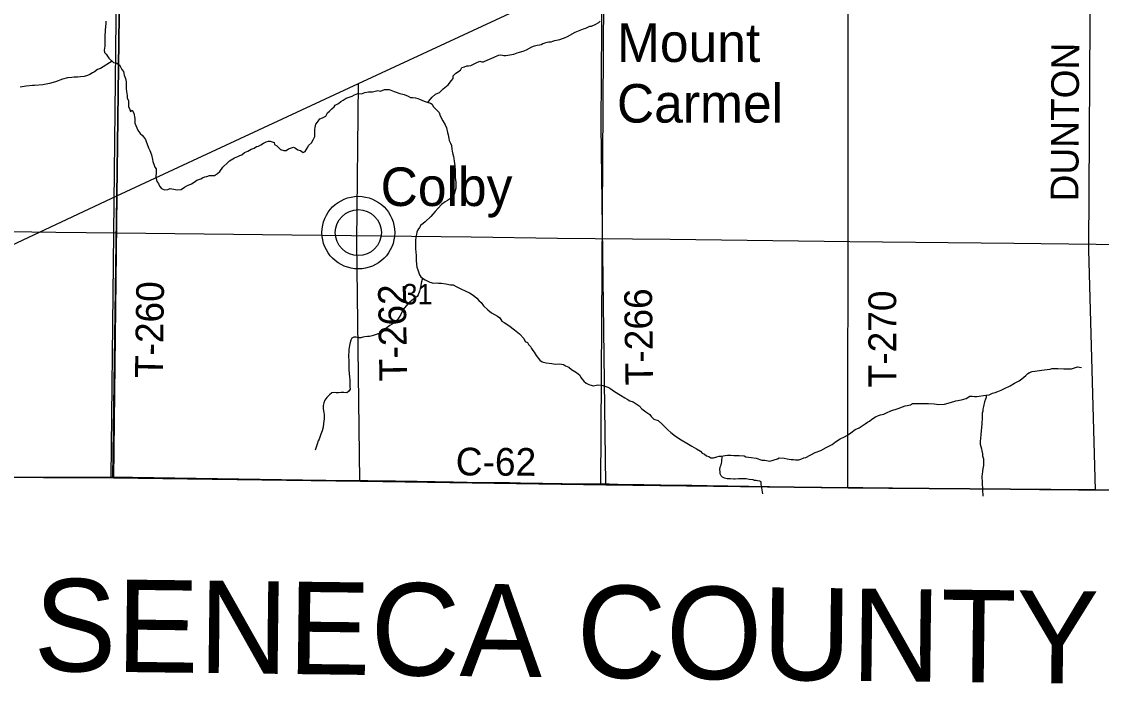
# Model space of a CAD drawing. Extents: x 1588073 to 2013523, y 1090242 to 1357120.
# Drawn here: x 1842074 to 1853753, y 1184232 to 1191391 of the extents above; entities that cross this region are included whole.
import ezdxf

# ---------------------------------------------------------------- set-up
doc = ezdxf.new("R2010")
doc.units = 0
for name, color, linetype in [('GM_X_Adjacent_County', 7, 'Continuous'), ('GM_X_Adjacent_County_Text', 7, 'Continuous'), ('GM_X_County', 7, 'Continuous'), ('GM_X_County_Road', 7, 'Continuous'), ('GM_X_County_Road_Text', 7, 'Continuous'), ('GM_X_Minor_River', 7, 'Continuous'), ('GM_X_Rail_Line', 7, 'Continuous'), ('GM_X_Section', 7, 'Continuous'), ('GM_X_Section_Text', 7, 'Continuous'), ('GM_X_Township', 7, 'Continuous'), ('GM_X_Township_Road', 7, 'Continuous'), ('GM_X_Township_Road_Text', 7, 'Continuous'), ('GM_X_Unincorporated', 7, 'Continuous'), ('GM_X_Unincorporated_Location', 7, 'Continuous'), ('GM_X_Unincorporated_Text', 7, 'Continuous')]:
    doc.layers.add(name, color=color, linetype=linetype)

msp = doc.modelspace()

# ---------------------------------------------------------------- linework, layer by layer
at = {"layer": 'GM_X_Adjacent_County'}
msp.add_lwpolyline([(1808199, 1186945), (1810942, 1186950), (1813328, 1186914), (1815460, 1186869), (1816005, 1186857), (1816631, 1186848), (1817077, 1186838), (1817700, 1186826), (1818180, 1186810), (1818871, 1186791), (1819168, 1186784), (1821835, 1186718), (1827562, 1186497), (1829633, 1186472), (1832499, 1186486), (1836614, 1186490), (1837772, 1186480), (1843068, 1186456), (1845738, 1186419), (1848393, 1186378), (1851014, 1186349), (1853645, 1186324), (1853690, 1186324), (1859011, 1186262)], dxfattribs=at)
at = {"layer": 'GM_X_County'}
msp.add_lwpolyline([(1859011, 1186262), (1853690, 1186324), (1853645, 1186324), (1851014, 1186349), (1848393, 1186378), (1845738, 1186419), (1843068, 1186456), (1837772, 1186480), (1836614, 1186490), (1832499, 1186486), (1829633, 1186472), (1827562, 1186497), (1821835, 1186718), (1819168, 1186784), (1818871, 1186791), (1818180, 1186810), (1817700, 1186826), (1817077, 1186838), (1816631, 1186848), (1816005, 1186857), (1815460, 1186869), (1813328, 1186914), (1810942, 1186950), (1808199, 1186945)], dxfattribs=at)
at = {"layer": 'GM_X_County_Road'}
for points in [[(1843105, 1189507), (1845717, 1190720), (1847202, 1191411), (1847662, 1191625), (1848323, 1191951), (1851017, 1193279)], [(1837774, 1187005), (1843105, 1189507)], [(1836617, 1186499), (1836629, 1186498), (1836740, 1186495), (1837115, 1186492), (1837367, 1186488), (1837499, 1186487), (1837760, 1186486), (1837991, 1186485), (1838381, 1186482), (1838864, 1186479), (1839379, 1186477), (1839648, 1186476), (1839977, 1186474), (1840154, 1186474), (1840466, 1186472), (1840866, 1186471), (1841335, 1186469), (1841608, 1186468), (1841825, 1186467), (1842586, 1186464), (1842776, 1186463), (1843060, 1186461)], [(1843060, 1186461), (1843072, 1186461), (1843777, 1186452), (1843879, 1186451), (1844266, 1186445), (1844558, 1186440), (1844749, 1186438), (1844985, 1186434), (1845366, 1186429), (1845733, 1186426), (1845819, 1186426), (1846117, 1186422), (1846354, 1186419), (1846741, 1186412), (1847046, 1186406), (1847256, 1186405), (1847351, 1186404), (1847591, 1186399), (1847709, 1186398), (1847919, 1186395), (1848247, 1186390), (1848375, 1186389), (1848394, 1186389)], [(1848394, 1186389), (1848428, 1186389), (1848615, 1186384), (1848805, 1186382), (1848989, 1186380), (1849189, 1186377), (1849324, 1186375), (1849488, 1186373), (1850164, 1186360), (1850315, 1186359), (1850508, 1186356), (1850728, 1186354), (1850951, 1186352), (1851010, 1186352), (1851171, 1186351), (1851492, 1186346), (1851843, 1186343), (1852093, 1186340), (1852569, 1186336), (1852815, 1186332), (1853084, 1186329), (1853504, 1186326), (1853637, 1186325), (1853689, 1186325)], [(1853689, 1186325), (1853747, 1186324), (1853980, 1186321), (1854220, 1186319), (1854505, 1186316), (1854725, 1186314), (1855017, 1186312), (1855303, 1186309), (1855657, 1186305), (1855893, 1186302), (1856034, 1186301), (1856454, 1186296), (1856947, 1186290), (1857291, 1186286), (1857551, 1186282), (1857757, 1186279), (1857899, 1186278), (1858056, 1186276), (1858197, 1186275), (1858342, 1186272), (1858526, 1186270), (1858729, 1186268), (1858890, 1186267), (1858998, 1186266)]]:
    msp.add_lwpolyline(points, dxfattribs=at)
at = {"layer": 'GM_X_Minor_River'}
for points in [[(1842986, 1191395), (1842984, 1191375), (1842982, 1191334), (1842978, 1191300), (1842978, 1191276), (1842976, 1191252), (1842975, 1191214), (1842975, 1191156), (1842973, 1191126), (1842971, 1191104), (1842967, 1191082), (1842971, 1191058), (1842988, 1191038), (1843018, 1190994), (1843068, 1190950), (1843104, 1190940), (1843134, 1190922), (1843159, 1190874), (1843177, 1190852), (1843181, 1190832), (1843183, 1190810), (1843197, 1190774), (1843206, 1190740), (1843206, 1190664), (1843210, 1190634), (1843214, 1190593), (1843216, 1190565), (1843229, 1190535), (1843229, 1190515), (1843231, 1190473), (1843243, 1190441), (1843251, 1190417), (1843271, 1190433), (1843289, 1190401), (1843300, 1190341), (1843300, 1190293), (1843308, 1190265), (1843330, 1190217), (1843357, 1190181), (1843383, 1190157), (1843415, 1190115), (1843421, 1190095), (1843431, 1190065), (1843446, 1190025), (1843462, 1189995), (1843478, 1189949), (1843490, 1189899), (1843494, 1189877), (1843509, 1189839), (1843515, 1189817), (1843529, 1189797), (1843531, 1189777), (1843531, 1189755), (1843527, 1189714), (1843529, 1189694), (1843538, 1189662), (1843554, 1189638), (1843564, 1189610), (1843586, 1189584), (1843618, 1189572), (1843654, 1189575), (1843682, 1189585), (1843739, 1189575), (1843761, 1189571), (1843799, 1189575), (1843837, 1189598), (1843869, 1189616), (1843911, 1189634), (1843939, 1189654), (1843968, 1189676), (1844011, 1189691), (1844031, 1189699), (1844054, 1189711), (1844079, 1189715), (1844105, 1189725), (1844131, 1189725), (1844161, 1189727), (1844191, 1189748), (1844217, 1189770), (1844252, 1189816), (1844304, 1189867), (1844324, 1189885), (1844378, 1189917), (1844414, 1189933), (1844436, 1189943), (1844456, 1189951), (1844486, 1189976), (1844520, 1189988), (1844558, 1190010), (1844590, 1190020), (1844616, 1190038), (1844636, 1190043), (1844660, 1190059), (1844692, 1190075), (1844720, 1190091), (1844744, 1190097), (1844764, 1190097), (1844784, 1190091)], [(1846465, 1190518), (1846475, 1190527), (1846515, 1190573), (1846551, 1190605), (1846595, 1190622), (1846634, 1190664), (1846670, 1190694), (1846686, 1190708), (1846723, 1190754), (1846741, 1190775), (1846743, 1190803), (1846771, 1190833), (1846820, 1190865), (1846836, 1190895), (1846864, 1190901), (1846890, 1190912), (1846906, 1190912), (1846934, 1190916), (1846991, 1190946), (1847029, 1190963), (1847051, 1190955), (1847069, 1190957), (1847083, 1190961), (1847133, 1190984), (1847185, 1191006), (1847232, 1191026), (1847250, 1191030), (1847274, 1191027), (1847290, 1191025), (1847310, 1191025), (1847332, 1191027), (1847396, 1191038), (1847434, 1191054), (1847458, 1191060), (1847498, 1191071), (1847534, 1191085), (1847591, 1191117), (1847621, 1191127), (1847649, 1191134), (1847675, 1191140), (1847693, 1191144), (1847711, 1191152), (1847727, 1191158), (1847743, 1191164), (1847757, 1191167), (1847777, 1191171), (1847801, 1191173), (1847820, 1191179), (1847842, 1191185), (1847894, 1191198), (1847924, 1191208), (1847946, 1191216), (1847978, 1191228), (1848061, 1191277), (1848097, 1191289), (1848151, 1191312), (1848175, 1191320), (1848221, 1191340), (1848237, 1191342), (1848278, 1191361), (1848316, 1191381), (1848330, 1191395)], [(1843052, 1190964), (1842926, 1190885), (1842894, 1190873), (1842862, 1190846), (1842840, 1190838), (1842812, 1190820), (1842788, 1190806), (1842752, 1190796), (1842710, 1190792), (1842678, 1190791), (1842644, 1190789), (1842616, 1190785), (1842572, 1190781), (1842518, 1190767), (1842442, 1190738), (1842374, 1190722), (1842302, 1190707), (1842214, 1190701), (1842192, 1190701), (1842123, 1190694), (1842057, 1190682)], [(1844784, 1190091), (1844804, 1190084), (1844810, 1190063), (1844834, 1190048), (1844855, 1190024), (1844875, 1190008), (1844909, 1189996), (1844935, 1189998), (1844959, 1190016), (1844983, 1190022), (1845015, 1190032), (1845035, 1190020), (1845063, 1190005), (1845089, 1189995), (1845121, 1189975), (1845141, 1189985), (1845151, 1190005), (1845171, 1190031), (1845177, 1190051), (1845211, 1190079), (1845229, 1190110), (1845245, 1190148), (1845244, 1190224), (1845250, 1190244), (1845258, 1190282), (1845276, 1190302), (1845300, 1190339), (1845330, 1190349), (1845366, 1190369), (1845384, 1190405), (1845404, 1190423), (1845428, 1190446), (1845454, 1190468), (1845466, 1190488), (1845500, 1190504), (1845525, 1190528), (1845551, 1190540), (1845583, 1190561), (1845605, 1190571), (1845649, 1190585), (1845675, 1190599), (1845709, 1190613), (1845752, 1190610), (1845788, 1190624), (1845826, 1190630), (1845870, 1190632), (1845926, 1190646), (1845956, 1190639), (1846000, 1190657), (1846022, 1190655), (1846050, 1190657), (1846104, 1190635), (1846166, 1190614), (1846213, 1190602), (1846255, 1190584), (1846281, 1190570), (1846307, 1190568), (1846335, 1190566), (1846359, 1190558), (1846379, 1190552), (1846429, 1190531), (1846461, 1190519), (1846496, 1190509), (1846516, 1190497), (1846524, 1190471), (1846558, 1190441), (1846590, 1190409), (1846601, 1190371), (1846631, 1190319), (1846655, 1190275), (1846669, 1190241), (1846682, 1190191), (1846686, 1190167), (1846696, 1190127), (1846700, 1190105), (1846714, 1190077), (1846722, 1190051), (1846729, 1190010), (1846731, 1189990), (1846739, 1189956), (1846745, 1189932), (1846749, 1189910), (1846753, 1189880), (1846758, 1189830), (1846762, 1189778), (1846762, 1189750), (1846764, 1189704), (1846768, 1189680), (1846770, 1189654), (1846771, 1189632), (1846769, 1189612), (1846769, 1189589), (1846765, 1189563), (1846755, 1189535), (1846733, 1189501), (1846701, 1189471), (1846681, 1189455), (1846655, 1189441), (1846617, 1189412), (1846580, 1189374), (1846548, 1189336)], [(1846548, 1189336), (1846520, 1189309), (1846500, 1189283), (1846440, 1189223), (1846416, 1189207), (1846392, 1189187), (1846376, 1189164), (1846360, 1189138), (1846350, 1189114), (1846346, 1189090), (1846339, 1189056), (1846335, 1189028), (1846333, 1188986), (1846335, 1188940), (1846339, 1188889), (1846342, 1188869), (1846342, 1188807), (1846344, 1188765), (1846350, 1188735), (1846358, 1188707), (1846367, 1188685), (1846377, 1188653), (1846391, 1188629), (1846419, 1188607), (1846439, 1188599), (1846491, 1188573), (1846529, 1188561), (1846556, 1188564), (1846584, 1188560), (1846614, 1188562), (1846664, 1188554), (1846712, 1188544), (1846742, 1188542), (1846774, 1188524), (1846826, 1188501), (1846879, 1188475), (1846917, 1188457), (1846959, 1188431), (1846997, 1188399), (1847021, 1188375), (1847044, 1188351), (1847070, 1188317), (1847116, 1188271), (1847158, 1188239), (1847221, 1188204), (1847245, 1188188), (1847269, 1188150), (1847293, 1188134), (1847343, 1188104), (1847406, 1188056), (1847460, 1188014), (1847505, 1187964), (1847521, 1187932), (1847545, 1187918), (1847557, 1187896), (1847577, 1187876), (1847589, 1187856), (1847603, 1187834), (1847618, 1187814), (1847638, 1187778), (1847680, 1187730), (1847704, 1187711), (1847748, 1187701), (1847809, 1187693), (1847845, 1187685), (1847889, 1187687), (1847913, 1187685), (1847935, 1187682), (1847957, 1187668), (1847991, 1187652), (1848023, 1187628), (1848076, 1187594), (1848110, 1187566), (1848124, 1187542), (1848138, 1187522), (1848154, 1187502), (1848180, 1187480), (1848200, 1187470), (1848221, 1187462), (1848259, 1187452), (1848307, 1187463), (1848337, 1187457), (1848361, 1187455), (1848393, 1187443), (1848413, 1187437), (1848435, 1187425), (1848487, 1187389), (1848550, 1187350), (1848600, 1187320), (1848624, 1187308), (1848654, 1187290), (1848690, 1187276), (1848731, 1187248), (1848755, 1187234), (1848783, 1187202), (1848825, 1187168), (1848868, 1187140), (1848884, 1187118), (1848912, 1187091), (1848958, 1187075), (1849002, 1187035)], [(1846410, 1188614), (1846397, 1188563), (1846393, 1188535), (1846385, 1188503), (1846378, 1188476), (1846364, 1188436), (1846352, 1188416), (1846308, 1188386), (1846276, 1188360), (1846250, 1188337), (1846202, 1188277), (1846190, 1188253), (1846176, 1188223), (1846159, 1188193), (1846135, 1188162), (1846111, 1188138), (1846083, 1188118), (1846057, 1188102), (1846029, 1188082), (1846005, 1188063), (1845975, 1188037), (1845953, 1188025), (1845929, 1188013), (1845887, 1187997), (1845867, 1187993), (1845835, 1187986), (1845815, 1187984), (1845785, 1187980), (1845765, 1187976), (1845743, 1187970), (1845719, 1187970), (1845693, 1187976), (1845669, 1187978), (1845647, 1187967), (1845635, 1187945), (1845627, 1187921), (1845621, 1187887), (1845617, 1187865), (1845615, 1187843), (1845613, 1187817), (1845611, 1187781), (1845612, 1187711), (1845614, 1187676), (1845614, 1187652), (1845614, 1187622), (1845621, 1187544), (1845623, 1187516), (1845623, 1187494), (1845625, 1187470), (1845625, 1187440), (1845627, 1187416), (1845611, 1187390), (1845591, 1187376), (1845559, 1187377), (1845531, 1187379), (1845501, 1187375), (1845475, 1187375), (1845455, 1187377), (1845431, 1187375), (1845403, 1187353), (1845375, 1187326), (1845353, 1187294), (1845343, 1187268), (1845336, 1187238), (1845334, 1187206), (1845340, 1187182), (1845344, 1187162), (1845348, 1187140), (1845348, 1187118), (1845346, 1187092), (1845339, 1187045), (1845335, 1187005), (1845325, 1186963), (1845311, 1186927), (1845299, 1186897), (1845291, 1186875), (1845283, 1186855), (1845270, 1186818), (1845262, 1186798), (1845250, 1186754)], [(1849002, 1187035), (1849065, 1186973), (1849095, 1186947), (1849147, 1186905), (1849208, 1186865), (1849268, 1186832), (1849322, 1186798), (1849374, 1186770), (1849417, 1186744), (1849433, 1186724), (1849461, 1186710), (1849483, 1186694), (1849505, 1186686), (1849527, 1186672), (1849557, 1186672), (1849595, 1186683), (1849617, 1186689), (1849637, 1186689), (1849710, 1186701), (1849744, 1186699), (1849778, 1186696), (1849812, 1186698), (1849836, 1186698), (1849888, 1186692), (1849908, 1186682), (1849966, 1186674), (1850018, 1186669), (1850079, 1186647), (1850111, 1186647), (1850165, 1186637), (1850249, 1186662), (1850269, 1186672), (1850323, 1186670), (1850355, 1186662), (1850375, 1186656), (1850399, 1186654), (1850423, 1186654), (1850445, 1186651), (1850481, 1186649), (1850503, 1186657), (1850535, 1186671), (1850557, 1186677), (1850657, 1186728), (1850717, 1186750), (1850775, 1186783), (1850839, 1186815), (1850877, 1186845), (1850929, 1186878), (1850975, 1186900), (1851007, 1186918), (1851043, 1186944), (1851091, 1186977), (1851133, 1186995), (1851155, 1187009), (1851199, 1187041), (1851223, 1187059), (1851245, 1187070), (1851269, 1187090), (1851311, 1187116), (1851343, 1187128), (1851363, 1187136), (1851401, 1187145), (1851427, 1187157), (1851477, 1187179), (1851553, 1187205), (1851603, 1187222), (1851631, 1187234), (1851653, 1187238), (1851687, 1187246), (1851709, 1187258), (1851765, 1187261), (1851787, 1187259), (1851881, 1187259), (1851945, 1187255), (1851996, 1187250), (1852056, 1187254), (1852122, 1187270), (1852178, 1187289), (1852238, 1187299), (1852290, 1187315), (1852330, 1187338), (1852354, 1187338), (1852380, 1187336), (1852404, 1187334), (1852502, 1187348), (1852540, 1187355), (1852576, 1187373), (1852604, 1187377), (1852632, 1187389), (1852668, 1187403), (1852706, 1187422), (1852766, 1187450), (1852814, 1187478), (1852862, 1187504), (1852892, 1187525), (1852914, 1187545), (1852936, 1187563), (1852956, 1187585), (1852976, 1187595), (1853002, 1187605), (1853032, 1187610)], [(1853032, 1187610), (1853058, 1187614), (1853134, 1187624), (1853198, 1187632), (1853218, 1187637), (1853280, 1187639), (1853346, 1187635), (1853387, 1187633), (1853431, 1187636), (1853471, 1187648), (1853495, 1187656), (1853515, 1187654), (1853537, 1187650)], [(1852507, 1187349), (1852506, 1187326), (1852500, 1187306), (1852488, 1187278), (1852477, 1187228), (1852471, 1187200), (1852469, 1187176), (1852463, 1187154), (1852463, 1187087), (1852461, 1187057), (1852458, 1187037), (1852456, 1187003), (1852452, 1186959), (1852448, 1186927), (1852444, 1186877), (1852442, 1186855), (1852443, 1186819), (1852447, 1186794), (1852455, 1186768), (1852459, 1186746), (1852465, 1186714), (1852465, 1186694), (1852476, 1186662), (1852478, 1186620), (1852476, 1186590), (1852470, 1186556), (1852468, 1186524), (1852462, 1186496), (1852460, 1186474), (1852471, 1186258)], [(1850090, 1186283), (1850076, 1186368), (1850074, 1186384), (1850074, 1186398), (1850072, 1186414), (1850058, 1186418), (1850034, 1186422), (1850018, 1186426), (1850000, 1186428), (1849986, 1186435), (1849942, 1186439), (1849912, 1186445), (1849860, 1186446), (1849826, 1186446), (1849792, 1186440), (1849778, 1186440), (1849742, 1186443), (1849724, 1186443), (1849706, 1186445), (1849692, 1186447), (1849676, 1186453), (1849656, 1186464), (1849640, 1186478), (1849631, 1186498), (1849629, 1186516), (1849625, 1186548), (1849629, 1186566), (1849633, 1186580), (1849639, 1186596), (1849644, 1186614), (1849646, 1186628), (1849651, 1186692)]]:
    msp.add_lwpolyline(points, dxfattribs=at)
at = {"layer": 'GM_X_Rail_Line'}
msp.add_lwpolyline([(1841662, 1189122), (1842445, 1189112), (1843102, 1189104), (1844995, 1189084), (1846935, 1189062), (1847871, 1189049), (1849087, 1189036), (1851031, 1189012), (1852804, 1188993), (1853696, 1188983), (1855356, 1188964)], dxfattribs=at)
at = {"layer": 'GM_X_Section'}
msp.add_lwpolyline([(1843101, 1191744), (1848366, 1191654), (1848334, 1186381), (1843042, 1186461)], close=True, dxfattribs=at)
at = {"layer": 'GM_X_Township'}
for points in [[(1822454, 1217980), (1826179, 1218043), (1826396, 1218046), (1832767, 1218132), (1832904, 1218134), (1838096, 1218217), (1843456, 1218285), (1843390, 1212953), (1843338, 1209236), (1843273, 1204127), (1843209, 1199148), (1843132, 1191734), (1843105, 1189507), (1843068, 1186456), (1837772, 1186480), (1836614, 1186490), (1832499, 1186486), (1829633, 1186472), (1827562, 1186497), (1821835, 1186718)], [(1859011, 1186262), (1853690, 1186324), (1853645, 1186324), (1851014, 1186349), (1848393, 1186378), (1845738, 1186419), (1843068, 1186456), (1843105, 1189507), (1843132, 1191734), (1843209, 1199148), (1843273, 1204127), (1843338, 1209236), (1843390, 1212953), (1843456, 1218285), (1848744, 1218244), (1854040, 1218203)]]:
    msp.add_lwpolyline(points, dxfattribs=at)
at = {"layer": 'GM_X_Township_Road'}
for points in [[(1853615, 1188940), (1853642, 1193230), (1853649, 1194371)], [(1851010, 1186352), (1851017, 1193279)], [(1848394, 1186389), (1848343, 1190268), (1848352, 1191871), (1848351, 1191893), (1848323, 1191951)], [(1843060, 1186461), (1843105, 1189507), (1843132, 1191734)], [(1845701, 1189013), (1845717, 1190720)], [(1845733, 1186426), (1845701, 1188996), (1845701, 1189013)], [(1853689, 1186325), (1853615, 1188919), (1853615, 1188940)]]:
    msp.add_lwpolyline(points, dxfattribs=at)
at = {"layer": 'GM_X_Unincorporated'}
for radius in [393, 249]:
    msp.add_circle((1845716, 1189108), radius, dxfattribs=at)
at = {"layer": 'GM_X_Unincorporated_Location'}
msp.add_line((1845716, 1189108), (1845716, 1189108), dxfattribs=at)

# ---------------------------------------------------------------- texts
at = {"layer": 'GM_X_Adjacent_County_Text'}
msp.add_text('SENECA COUNTY', height=1000, rotation=359.3055, dxfattribs=at).set_placement((1842202, 1184367))
at = {"layer": 'GM_X_County_Road_Text'}
msp.add_text('C-62', height=300, rotation=359.6636, dxfattribs=at).set_placement((1846769, 1186482))
at = {"layer": 'GM_X_Section_Text'}
msp.add_text('31', height=221, rotation=0, dxfattribs=at).set_placement((1846192, 1188332))
at = {"layer": 'GM_X_Township_Road_Text'}
for s, rotation, p in [('DUNTON', 89.6746, (1853503, 1189445)), ('T-260', 89.1579, (1843600, 1187532)), ('T-262', 90.8421, (1846244, 1187503)), ('T-266', 90.8421, (1848906, 1187459)), ('T-270', 90, (1851533, 1187434))]:
    msp.add_text(s, height=300, rotation=rotation, dxfattribs=at).set_placement(p)
at = {"layer": 'GM_X_Unincorporated_Text'}
for s, p in [('Mount', (1848513, 1190954)), ('Carmel', (1848513, 1190298)), ('Colby', (1845957, 1189396))]:
    msp.add_text(s, height=417, rotation=0, dxfattribs=at).set_placement(p)

doc.saveas('drawing.dxf')
